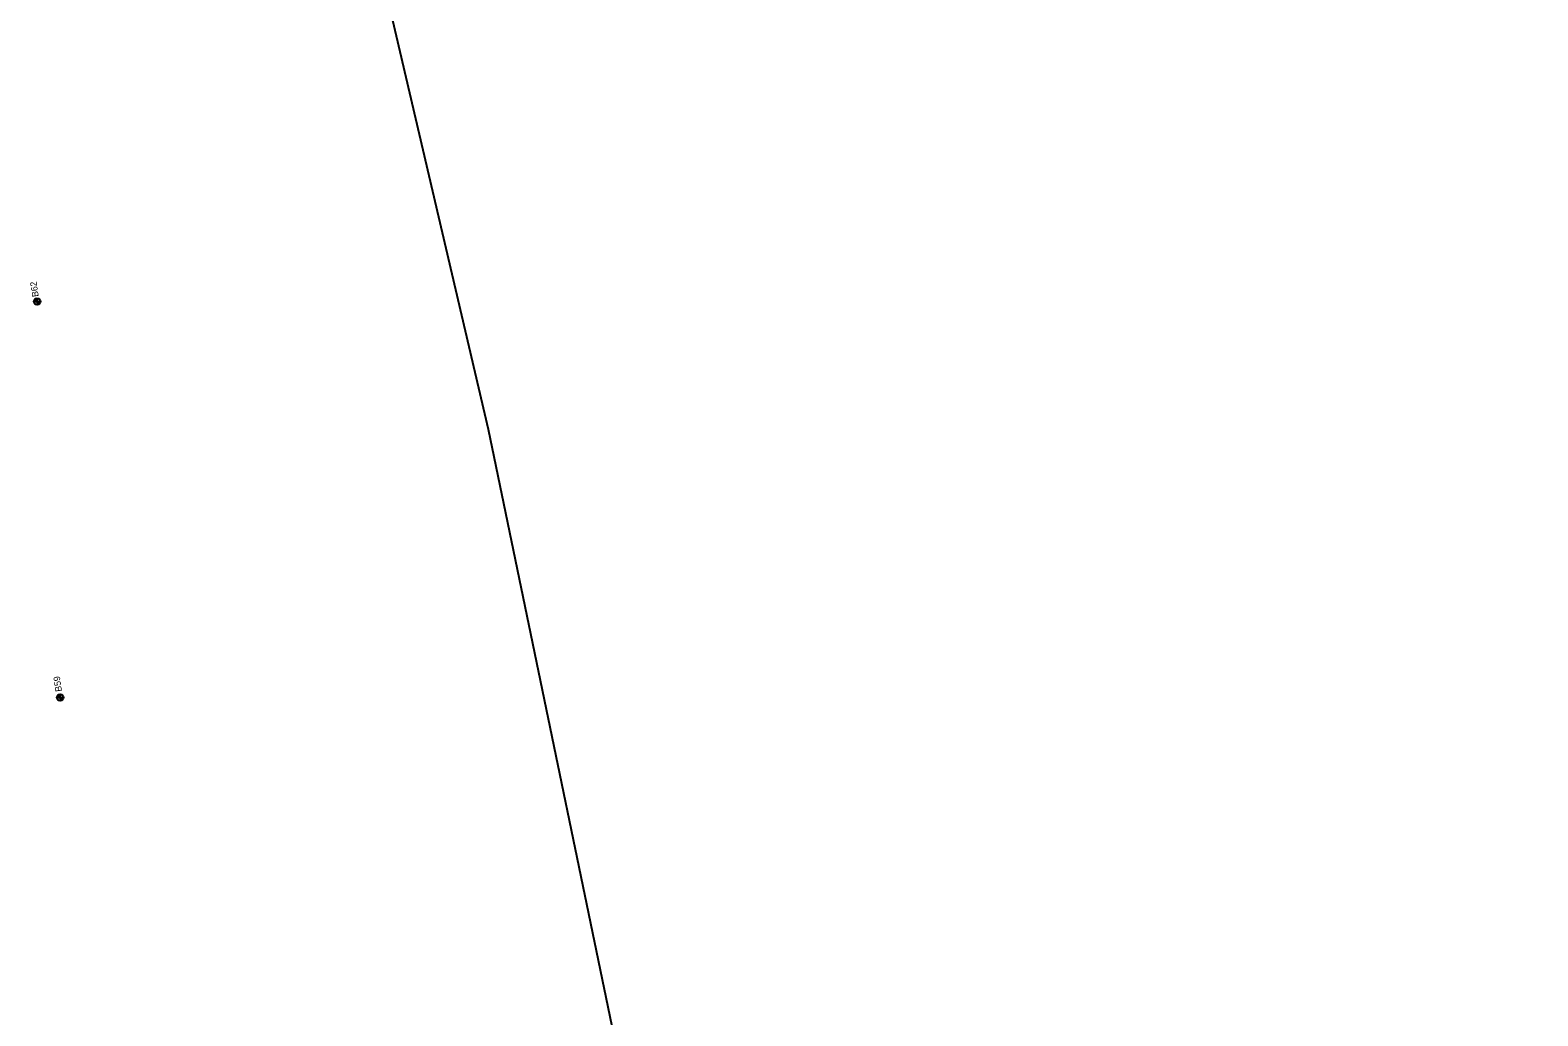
# Model space of a CAD drawing. Extents: x 311409 to 379449, y 121539 to 224848.
# Drawn here: x 359651 to 361967, y 162391 to 163905 of the extents above; entities that cross this region are included whole.
import ezdxf

# ---------------------------------------------------------------- set-up
doc = ezdxf.new("R2010")
doc.units = 0
for name, color, linetype in [('E_SOIL_BORE2 [KAPUR_CADDS_LEVELS]', 7, 'Continuous'), ('P_MARK', 7, 'Continuous'), ('P_TC', 7, 'Continuous')]:
    doc.layers.add(name, color=color, linetype=linetype)

msp = doc.modelspace()

# ---------------------------------------------------------------- linework, layer by layer
at = {"layer": 'P_MARK'}
for p, q in [((359661.6, 163492.9), (359661.6, 163482.9)), ((359656.6, 163487.9), (359666.6, 163487.9)), ((359692, 162879.9), (359702, 162879.9)), ((359697, 162884.9), (359697, 162874.9))]:
    msp.add_line(p, q, dxfattribs=at)
for centre in [(359661.6, 163487.9), (359697, 162879.9)]:
    msp.add_circle(centre, 5, dxfattribs=at)
for centre, radius, start, end in [((359661.6, 163487.9), 4.5, 89.9869, 179.9869), ((359661.6, 163487.9), 4, 89.9869, 179.9869), ((359661.6, 163487.9), 3.5, 89.9869, 179.9869), ((359661.6, 163487.9), 3, 89.9869, 179.9869), ((359661.6, 163487.9), 2.5, 89.9869, 179.9869), ((359661.6, 163487.9), 2, 89.9869, 179.9869), ((359661.6, 163487.9), 1.5, 89.9869, 179.9869), ((359661.6, 163487.9), 1, 89.9869, 179.9869), ((359661.6, 163487.9), 0.5, 89.9869, 179.9869), ((359661.6, 163487.9), 4.5, 269.9869, 359.9869), ((359661.6, 163487.9), 4, 269.9869, 359.9869), ((359661.6, 163487.9), 3.5, 269.9869, 359.9869), ((359661.6, 163487.9), 3, 269.9869, 359.9869), ((359661.6, 163487.9), 2.5, 269.9869, 359.9869), ((359661.6, 163487.9), 2, 269.9869, 359.9869), ((359661.6, 163487.9), 1.5, 269.9869, 359.9869), ((359661.6, 163487.9), 1, 269.9869, 359.9869), ((359661.6, 163487.9), 0.5, 269.9869, 359.9869), ((359697, 162879.9), 4.5, 89.9869, 179.9869), ((359697, 162879.9), 4, 89.9869, 179.9869), ((359697, 162879.9), 3.5, 89.9869, 179.9869), ((359697, 162879.9), 3, 89.9869, 179.9869), ((359697, 162879.9), 2.5, 89.9869, 179.9869), ((359697, 162879.9), 2, 89.9869, 179.9869), ((359697, 162879.9), 1.5, 89.9869, 179.9869), ((359697, 162879.9), 1, 89.9869, 179.9869), ((359697, 162879.9), 0.5, 89.9869, 179.9869), ((359697, 162879.9), 4.5, 269.9869, 359.9869), ((359697, 162879.9), 4, 269.9869, 359.9869), ((359697, 162879.9), 3.5, 269.9869, 359.9869), ((359697, 162879.9), 3, 269.9869, 359.9869), ((359697, 162879.9), 2.5, 269.9869, 359.9869), ((359697, 162879.9), 2, 269.9869, 359.9869), ((359697, 162879.9), 1.5, 269.9869, 359.9869), ((359697, 162879.9), 1, 269.9869, 359.9869), ((359697, 162879.9), 0.5, 269.9869, 359.9869)]:
    msp.add_arc(centre, radius, start, end, dxfattribs=at)
at = {"layer": 'P_TC'}
msp.add_lwpolyline([(361967.2, 148742.4), (361289.2, 151524), (361150.4, 152029.3), (361085.6, 152465.4), (360932.2, 153930.3), (360925.6, 158686.2), (360924.7, 159340.4), (360899.9, 160010), (360888, 160413.6), (360826.8, 160968.6), (360595.4, 162132.3), (360355.1, 163291.2), (360178.1, 164047.2)], dxfattribs=at)

# ---------------------------------------------------------------- texts
at = {"layer": 'E_SOIL_BORE2 [KAPUR_CADDS_LEVELS]'}
for s, p in [('B62', (359664, 163495.8)), ('B59', (359699.7, 162889.5))]:
    msp.add_text(s, height=10, rotation=98.5151, dxfattribs=at).set_placement(p)

doc.saveas('drawing.dxf')
